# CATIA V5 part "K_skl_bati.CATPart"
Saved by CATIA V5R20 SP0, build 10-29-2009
Part number: skl_bati
Publications: "Axe_bati_guidon", "Plan_bati_guidon", "Axe_bati_arriere", "Plan_bati"
Bounding box of the stored display mesh (mm): x 0 to 0, y 0 to 200, z 0 to 370
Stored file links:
  G:\Khaled_CFAO_2011\SIL\SIL_GR2\ahabrial\ahabrial\Khaled\CAD_ThinkMOTION\K_skl_bati.CATPart
  G:\Données\Ecole\IFMA\2A\Thinkmotion2\Etape18\trotinette.CATProduct
  G:\Khaled_CFAO_2011\SIL\SIL_GR2\ahabrial\ahabrial\Khaled\CAD_ThinkMOTION\K_skl_guidon.CATPart
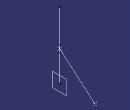
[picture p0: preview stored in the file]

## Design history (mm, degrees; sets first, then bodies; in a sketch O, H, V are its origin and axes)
Set1
  Point1: linked copy from another document
  Point2: linked copy from another document
  Line1: linked copy from another document
  Plane1 "Plan_ref": linked copy from another document
Body1 (main body)
  Line2 "Droite_bati": type PtPt, FirstPoint Point1, SecondPoint Point2
  Line3 "Axe_bati_guidon": type PtDir, RefPoint Point1, Direction Line1, Start -20, End 20
  Plane2 "Plan_bati_guidon": type Normal, Curve Line3, RefPoint Point1
  Line4 "Axe_bati_arriere": type Normal, RefPoint Point2, RefSkin Plane1, Start -20, End 20
  Plane3 "Plan_bati": type Normal, Curve Line2, RefPoint Point2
